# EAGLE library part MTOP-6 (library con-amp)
AMP connector
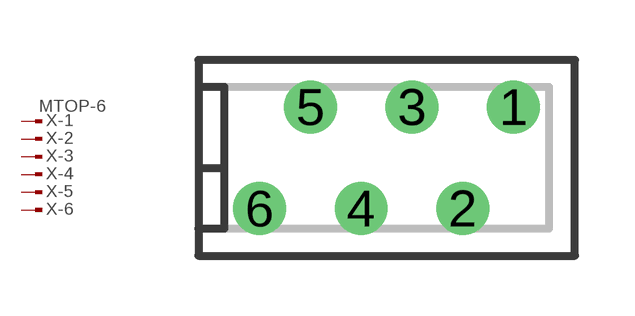
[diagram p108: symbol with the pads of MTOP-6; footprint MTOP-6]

Designator prefix X; gates -1=PIN-MV -2=PIN-M -3=PIN-M -4=PIN-M -5=PIN-M -6=PIN-M

## MTOP-6 (OC_FARNELL: unknown; OC_NEWARK: unknown)  [MTOP-6]
1  -1:1  pas
2  -2:1  pas
3  -3:1  pas
4  -4:1  pas
5  -5:1  pas
6  -6:1  pas

## Footprint MTOP-6 (pad centres in mm)
AMP connector
drill 0.813 round: 1 3.175,1.27; 2 1.905,-1.27; 3 0.635,1.27; 4 -0.635,-1.27; 5 -1.905,1.27; 6 -3.175,-1.27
